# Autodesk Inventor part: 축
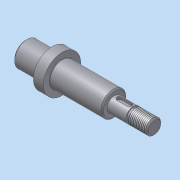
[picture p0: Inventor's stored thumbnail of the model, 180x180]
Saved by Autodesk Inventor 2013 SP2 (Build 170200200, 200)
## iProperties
Created: 2015-03
Part Number: 축
Material: 강
Document SubType Name: Modeling
Designer: KYOUNG IL JANG
Density: 1 g/cm^3
CustomPartVersion: 1
Author: KYOUNG IL JANG
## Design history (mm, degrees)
sketch "스케치5"
  geometry: L1 (0, 0)-(103, 0); L2 (0, 0)-(103, 0); L3 (103, 0)-(103, 6); L4 (71, 6)-(71, 10); L5 (71, 10)-(29, 10); L6 (29, 10)-(29, 15); L7 (29, 15)-(21, 15); L8 (21, 15)-(21, 10); L9 (21, 10)-(0, 10); L10 (0, 10)-(0, 0); L11 (86, 6)-(86, 5); L12 (86, 5)-(88, 5); L13 (88, 5)-(88, 6); L14 (103, 6)-(88, 6); L15 (86, 6)-(71, 6)
  constraints: 31 end point, 12 perpendicular, 9 parallel, 1 collinear, 1 horizontal
  dimensions: "d43" = 20 diameter of L9 L1; "d44" = 30 diameter of L7 L1; "d45" = 20 diameter of L5 L2; "d47" = 8 distance of L6.end L7.end; "d48" = 32 distance between parallel lines of L3 L4; "d49" = 42 distance between parallel lines of L4 L6; "d50" = 21 distance of L8.end L9.end; "d52" = 12 diameter of L14 L1; "d53" = 15 distance between parallel lines of L3 L13; "d54" = 2 distance of L11.end L12.end; "d55" = 1 distance between parallel lines of L14 L12
revolve "회전4" sketch "스케치5" stored, may be unused: angle "d51" = 90 deg
feature "스레드6" dims "d56" = 10, "d57" = 0
chamfer "모따기6" distance "d32" = 1; stored, may be unused: second distance "d33" = 0.4, angle "d34" = 45 deg
chamfer "모따기5" distance "d27" = 1; stored, may be unused: second distance "d28" = 0.125, angle "d29" = 45 deg
fillet "모깎기1" dims "d17" = 0.3
fillet "모깎기2" dims "d18" = 0.3
chamfer "모따기3" distance "d19" = 1; stored, may be unused: second distance "d20" = 1, angle "d21" = 45 deg
node "작업 평면1"
sketch "스케치6"
  geometry: L1 (-3.5, 2)-(4.5, 2); L2 (4.5, -2)-(-3.5, -2); L3 (-7.5, 9)-(-7.5, -9) reference; A1 r 2 centre (4.5, 0) between (4.5, -2) and (4.5, 2); A2 r 2 centre (-3.5, 0) between (-3.5, 2) and (-3.5, -2); 1 further point
  constraints: 4 end point, 4 point on circle, 4 tangent, 2 centre point, 1 horizontal, 1 horizontal alignment, 1 parallel
  dimensions: "d59" = 2 distance edge to line of A2 L3; "d60" = 12 dimension on A1 A2; "d61" = 4 distance between parallel lines of L2 L1
extrude "돌출1" cut sketch "스케치6" distance "d62" = 2.3; taper "d63" = 0 deg
node "솔리드1"
node "솔리드2"
other parameters: "d46" = 12
